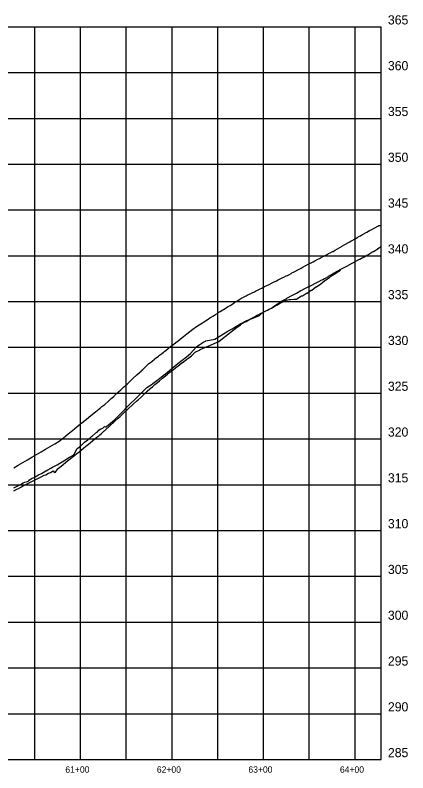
# Model space of a CAD drawing. Extents: x 816928 to 825690, y 436959 to 448212.
# Drawn here: x 818316 to 818745, y 446423 to 447250 of the extents above; entities that cross this region are included whole.
import ezdxf

# ---------------------------------------------------------------- set-up
doc = ezdxf.new("R2010")
doc.units = 0
for name, color, linetype in [('DESIGN - SHEET - Corner Text', 7, 'Continuous'), ('DESIGN - SHEET - Light Grid', 7, 'Continuous'), ('SURVEY - PROFILE - Ground Line with Text', 7, 'Continuous'), ('SURVEY - PROFILE - Utilities - Gas with Text', 7, 'Continuous'), ('SURVEY - PROFILE - Utilities - Water with Text', 7, 'Continuous')]:
    doc.layers.add(name, color=color, linetype=linetype)

msp = doc.modelspace()

# ---------------------------------------------------------------- linework, layer by layer
at = {"layer": 'DESIGN - SHEET - Light Grid'}
for p, q in [((817287.73, 447237.63), (818716.11, 447237.63)), ((817287.73, 447237.63), (818716.11, 447237.63)), ((818337.73, 446437.63), (818337.73, 447237.63)), ((818387.73, 446437.63), (818387.73, 447237.63)), ((818437.73, 446437.63), (818437.73, 447237.63)), ((818487.73, 446437.63), (818487.73, 447237.63)), ((818537.73, 446437.63), (818537.73, 447237.63)), ((818587.73, 446437.63), (818587.73, 447237.63)), ((818637.73, 446437.63), (818637.73, 447237.63)), ((818687.73, 446437.63), (818687.73, 447237.63)), ((818716.11, 446437.63), (818716.11, 447237.63)), ((817287.73, 447187.63), (818716.11, 447187.63)), ((817287.73, 447137.63), (818716.11, 447137.63)), ((817287.73, 447087.63), (818716.11, 447087.63)), ((817287.73, 447037.63), (818716.11, 447037.63)), ((817287.73, 446987.63), (818716.11, 446987.63)), ((817287.73, 446937.63), (818716.11, 446937.63)), ((817287.73, 446887.63), (818716.11, 446887.63)), ((817287.73, 446837.63), (818716.11, 446837.63)), ((817287.73, 446787.63), (818716.11, 446787.63)), ((817287.73, 446737.63), (818716.11, 446737.63)), ((817287.73, 446687.63), (818716.11, 446687.63)), ((817287.73, 446637.63), (818716.11, 446637.63)), ((817287.73, 446587.63), (818716.11, 446587.63)), ((817287.73, 446537.63), (818716.11, 446537.63)), ((817287.73, 446487.63), (818716.11, 446487.63)), ((817287.73, 446437.63), (818716.11, 446437.63)), ((817287.73, 446437.63), (818716.11, 446437.63))]:
    msp.add_line(p, q, dxfattribs=at)
at = {"layer": 'SURVEY - PROFILE - Ground Line with Text'}
msp.add_lwpolyline([(818314.72, 446756.01), (818319.71, 446758.93), (818324.7, 446761.85), (818329.68, 446764.77), (818334.67, 446767.69), (818339.66, 446770.62), (818344.65, 446773.54), (818349.63, 446776.46), (818354.62, 446779.39), (818359.61, 446782.31), (818364.59, 446785.25), (818369.19, 446788.98), (818374.15, 446792.99), (818378.94, 446796.88), (818384.1, 446801.03), (818389.14, 446805.1), (818394.15, 446809.16), (818399.17, 446813.22), (818404.19, 446817.29), (818407.67, 446820.1), (818409.21, 446821.36), (818411.1, 446822.9), (818414.21, 446825.19), (818414.53, 446825.48), (818417.97, 446828.59), (818419, 446829.53), (818419.32, 446829.84), (818421.4, 446831.73), (818423.98, 446834.08), (818424.35, 446834.45), (818424.83, 446834.88), (818428.26, 446838.02), (818428.96, 446838.65), (818429.37, 446839.06), (818431.69, 446841.18), (818433.94, 446843.24), (818434.38, 446843.68), (818435.12, 446844.36), (818438.56, 446847.5), (818438.92, 446847.84), (818439.38, 446848.3), (818441.99, 446850.69), (818443.89, 446852.44), (818444.37, 446852.92), (818445.42, 446853.88), (818448.87, 446857.06), (818449.35, 446857.54), (818452.28, 446860.24), (818453.85, 446861.68), (818454.33, 446862.16), (818455.71, 446863.44), (818458.83, 446866.31), (818459.29, 446866.77), (818462.58, 446869.8), (818464.08, 446871.15), (818466.01, 446872.65), (818468.6, 446874.66), (818469.06, 446875.03), (818469.44, 446875.32), (818472.87, 446877.99), (818473.56, 446878.53), (818474.05, 446878.91), (818476.3, 446880.67), (818478.54, 446882.41), (818479.03, 446882.8), (818479.74, 446883.35), (818483.17, 446886.02), (818483.52, 446886.3), (818484.02, 446886.69), (818486.6, 446888.71), (818488.51, 446890.2), (818489, 446890.59), (818490.03, 446891.39), (818493.52, 446894.11), (818493.99, 446894.48), (818496.89, 446896.75), (818498.53, 446898.03), (818498.97, 446898.38), (818500.33, 446899.44), (818503.96, 446902.28), (818507.19, 446904.81), (818508.59, 446905.9), (818508.94, 446906.19), (818510.62, 446907.5), (818514.3, 446910.31), (818517.48, 446912.32), (818519.24, 446913.42), (818520.92, 446914.48), (818524.44, 446916.69), (818527.1, 446918.37), (818529.12, 446919.64), (818529.77, 446920.05), (818532.44, 446921.73), (818534.07, 446922.76), (818535.11, 446923.41), (818537.78, 446925.09), (818538.44, 446925.51), (818539.04, 446925.88), (818540.45, 446926.75), (818543.12, 446928.41), (818544.04, 446928.99), (818545.79, 446930.08), (818548.46, 446931.75), (818549.04, 446932.12), (818551.13, 446933.42), (818554.02, 446935.25), (818556.46, 446936.79), (818558.58, 446938.12), (818559.13, 446938.47), (818561.8, 446940.13), (818563.99, 446941.49), (818564.47, 446941.73), (818567.14, 446943.08), (818567.91, 446943.47), (818568.82, 446943.92), (818569.81, 446944.41), (818572.48, 446945.73), (818573.85, 446946.41), (818575.15, 446947.05), (818577.82, 446948.38), (818578.86, 446948.91), (818580.48, 446949.71), (818583.15, 446951.04), (818583.86, 446951.4), (818585.82, 446952.38), (818588.85, 446953.9), (818591.16, 446955.05), (818593.83, 446956.39), (818596.5, 446957.73), (818598.78, 446958.87), (818599.28, 446959.12), (818601.84, 446960.38), (818603.81, 446961.35), (818604.51, 446961.69), (818607.17, 446963), (818608.86, 446963.83), (818609.84, 446964.31), (818612.51, 446965.61), (818613.82, 446966.21), (818615.18, 446966.94), (818617.85, 446968.37), (818618.73, 446968.78), (818620.52, 446969.74), (818623.19, 446971.18), (818623.7, 446971.41), (818625.86, 446972.58), (818628.71, 446974.12), (818631.2, 446975.44), (818633.86, 446976.86), (818636.53, 446978.26), (818638.67, 446979.39), (818639.2, 446979.67), (818641.87, 446981.06), (818643.68, 446982.01), (818644.54, 446982.46), (818647.21, 446983.85), (818648.69, 446984.63), (818649.88, 446985.24), (818652.55, 446986.62), (818653.72, 446987.25), (818655.22, 446988.02), (818657.88, 446989.4), (818658.77, 446989.89), (818660.55, 446990.81), (818663.22, 446992.19), (818663.63, 446992.41), (818665.89, 446993.7), (818668.57, 446995.23), (818671.23, 446996.75), (818673.56, 446998.08), (818673.9, 446998.27), (818676.57, 446999.8), (818678.55, 447000.92), (818679.24, 447001.31), (818681.91, 447002.83), (818683.54, 447003.76), (818684.57, 447004.34), (818687.24, 447005.86), (818688.53, 447006.58), (818689.91, 447007.36), (818692.58, 447008.87), (818693.53, 447009.4), (818695.25, 447010.37), (818697.92, 447011.87), (818698.52, 447012.21), (818700.59, 447013.37), (818703.53, 447015.01), (818705.93, 447016.35), (818708.53, 447017.8), (818713.19, 447020.4), (818713.53, 447020.59), (818716.11, 447020.6)], dxfattribs=at)
at = {"layer": 'SURVEY - PROFILE - Utilities - Gas with Text'}
msp.add_lwpolyline([(818315, 446734.29), (818317.06, 446735.25), (818319.99, 446736.9), (818322.04, 446737.84), (818324.99, 446739.51), (818327.02, 446740.45), (818329.67, 446741.04), (818331.31, 446741.8), (818331.99, 446743.05), (818334.98, 446744.74), (818336.97, 446745.66), (818339.97, 446747.36), (818341.95, 446748.28), (818344.97, 446749.98), (818346.93, 446750.9), (818349.96, 446752.61), (818350.23, 446752.76), (818352.21, 446753.84), (818355.22, 446755.54), (818357.23, 446756.63), (818360.21, 446758.32), (818362.24, 446759.42), (818365.2, 446761.09), (818365.75, 446761.47), (818367.81, 446762.59), (818370.72, 446764.58), (818372.89, 446765.76), (818375.68, 446767.67), (818377.96, 446768.89), (818380.65, 446770.72), (818383.73, 446776.86), (818386.41, 446778.79), (818387.8, 446780.01), (818388.39, 446780.54), (818388.39, 446780.54), (818390.4, 446782.35), (818392.26, 446784.02), (818395.64, 446786.58), (818399.69, 446790.25), (818400.55, 446790.8), (818404.42, 446794.31), (818405.9, 446795.12), (818407.67, 446797.04), (818409.29, 446798.23), (818412.01, 446799.22), (818413.99, 446801.08), (818415.73, 446800.58), (818416.23, 446801.08), (818418.25, 446803.12), (818424.93, 446808.5), (818429.35, 446812.93), (818433.75, 446817.35), (818438.15, 446821.77), (818442.54, 446826.18), (818446.93, 446830.59), (818451.31, 446834.98), (818455.68, 446839.37), (818460.04, 446843.76), (818466.05, 446847.51), (818466.62, 446847.95), (818471.28, 446851.57), (818475.92, 446855.17), (818478, 446856.79), (818480.51, 446858.8), (818485.08, 446862.48), (818489.66, 446866.15), (818494.23, 446869.83), (818498.82, 446873.52), (818503.4, 446877.2), (818507.99, 446880.89), (818514.01, 446887.95), (818516.26, 446889.75), (818517.99, 446890.79), (818520.25, 446892.15), (818522.51, 446893.51), (818524.35, 446894.43), (818524.44, 446894.49), (818524.77, 446894.87), (818534.47, 446896.7), (818539.22, 446899.5), (818543.97, 446902.3), (818548.72, 446905.1), (818553.47, 446907.9), (818558.22, 446910.7), (818562.96, 446913.5), (818564.6, 446914.4), (818568, 446916.29), (818569.37, 446916.82), (818574.1, 446918.66), (818578.8, 446920.48), (818583.45, 446922.29), (818587.7, 446926.28), (818592.22, 446928.16), (818593.03, 446928.94), (818597.26, 446930.73), (818600.74, 446933.16), (818602.1, 446933.75), (818602.9, 446934.18), (818604.09, 446934.82), (818607.21, 446936.5), (818610.19, 446938.11), (818611.1, 446938.6), (818615.9, 446939.69), (818617.38, 446939.79), (818617.53, 446939.8), (818620.73, 446940.03), (818622.54, 446940.16), (818623.99, 446940.27), (818624.75, 446940.8), (818626.31, 446941.9), (818629.04, 446943.84), (818630.41, 446943.81), (818634.48, 446946.71), (818635.35, 446946.86), (818639.72, 446950), (818640.38, 446950.2), (818644.94, 446953.48), (818645.46, 446953.68), (818650.14, 446957.05), (818650.16, 446957.06), (818654.87, 446960.46), (818655.29, 446960.81), (818660.09, 446964.27), (818660.97, 446964.84), (818661.32, 446965.13), (818666.56, 446968.51), (818666.82, 446968.72), (818669.94, 446970.73), (818671.91, 446971.77)], dxfattribs=at)
at = {"layer": 'SURVEY - PROFILE - Utilities - Water with Text'}
msp.add_lwpolyline([(818314.92, 446731.06), (818318.22, 446732.88), (818319.23, 446733.29), (818323.19, 446735.47), (818324.29, 446735.92), (818328.15, 446738.03), (818329.37, 446738.52), (818333.12, 446740.56), (818334.44, 446741.09), (818338.08, 446743.06), (818339.52, 446743.62), (818339.79, 446743.64), (818343.15, 446745.45), (818344.61, 446746.12), (818348, 446747.94), (818349.7, 446748.58), (818352.95, 446750.32), (818354.79, 446751), (818357.91, 446752.65), (818359.45, 446750.82), (818360.51, 446751.24), (818362.86, 446754.94), (818363.77, 446755.69), (818366.52, 446757.82), (818368.64, 446759.6), (818371.44, 446761.76), (818373.64, 446763.61), (818376.35, 446765.7), (818378.64, 446767.63), (818381.26, 446769.66), (818383.64, 446771.67), (818386.16, 446773.62), (818388.65, 446775.72), (818391.06, 446777.59), (818393.65, 446779.79), (818395.96, 446781.58), (818398.66, 446783.88), (818400.84, 446785.58), (818403.66, 446787.99), (818405.72, 446789.59), (818407.67, 446791.11), (818408.68, 446792.12), (818410.62, 446793.62), (818413.73, 446796.28), (818413.87, 446796.41), (818415.56, 446798), (818418.76, 446800.92), (818420.58, 446802.63), (818423.77, 446805.55), (818425.59, 446807.26), (818428.78, 446810.18), (818430.61, 446811.89), (818433.8, 446814.81), (818435.62, 446816.52), (818438.81, 446819.44), (818440.64, 446821.16), (818443.83, 446824.07), (818445.66, 446825.79), (818448.84, 446828.7), (818450.67, 446830.42), (818453.85, 446833.33), (818455.69, 446835.06), (818458.87, 446837.96), (818460.7, 446839.69), (818463.43, 446842.22), (818463.87, 446842.57), (818466.29, 446844.53), (818468.87, 446846.88), (818471.82, 446849.24), (818473.88, 446851.09), (818477.31, 446853.8), (818478.89, 446855.2), (818482.75, 446858.22), (818483.9, 446859.23), (818488.15, 446862.54), (818488.91, 446863.2), (818491.68, 446865.34), (818493.43, 446866.65), (818493.92, 446867.06), (818498.53, 446870.52), (818498.93, 446870.86), (818503.61, 446874.36), (818503.95, 446874.64), (818504.48, 446875.01), (818508.98, 446878.38), (818513.56, 446882.64), (818513.81, 446882.87), (818518.35, 446885.01), (818518.52, 446885.12), (818518.66, 446885.18), (818523.47, 446887.43), (818523.97, 446887.65), (818524.01, 446887.66), (818524.35, 446887.93), (818524.44, 446887.97), (818528.89, 446889.77), (818528.92, 446889.79), (818533.8, 446891.9), (818533.87, 446891.95), (818538.71, 446894.05), (818538.82, 446894.12), (818542.75, 446897.19), (818542.89, 446897.28), (818547.67, 446900.99), (818547.84, 446901.1), (818552.58, 446904.79), (818552.79, 446904.92), (818557.49, 446908.57), (818557.74, 446908.73), (818562.41, 446912.35), (818562.69, 446912.53), (818563.74, 446913.11), (818568.49, 446915.77), (818568.68, 446915.86), (818573.51, 446918.57), (818573.62, 446918.63), (818578.54, 446921.39), (818578.56, 446921.4), (818580.03, 446922.22), (818583.44, 446923.95), (818583.72, 446924.09), (818588.3, 446926.41), (818588.73, 446926.62), (818592.85, 446928.71), (818593.82, 446929.2), (818596.42, 446930.51), (818597.76, 446931.42), (818598.71, 446932.07), (818603.06, 446935.02), (818603.42, 446935.26), (818606.41, 446937.29), (818608.18, 446938.31), (818608.23, 446938.33), (818613.01, 446941.07), (818613.18, 446941.15), (818613.77, 446941.48), (818618.6, 446944.12), (818618.71, 446944.19), (818623.6, 446946.87), (818623.66, 446946.9), (818628.6, 446949.61), (818628.6, 446949.61), (818628.92, 446949.79), (818633.46, 446952.14), (818633.58, 446952.22), (818633.61, 446952.2), (818634.97, 446952.88), (818639.68, 446955.21), (818639.83, 446955.28), (818644.54, 446957.62), (818645.05, 446957.98), (818649.77, 446960.35), (818649.99, 446960.46), (818652.57, 446961.76), (818654.43, 446962.84), (818654.7, 446962.62), (818658.58, 446965.1), (818658.8, 446965.21), (818663.68, 446968.35), (818663.71, 446968.37), (818668.03, 446970.67), (818668.11, 446970.72), (818672.93, 446973.29), (818673.07, 446973.36), (818677.83, 446975.9), (818678.03, 446976.01), (818682.72, 446978.51), (818682.99, 446978.65), (818687.62, 446981.12), (818687.95, 446981.3), (818692.51, 446983.73), (818692.91, 446983.94), (818697.4, 446986.34), (818697.87, 446986.58), (818700.73, 446988.11), (818702.33, 446989.1), (818702.81, 446989.39), (818705.93, 446991.33), (818707.39, 446992.21), (818707.74, 446992.42), (818712.49, 446995.32), (818712.7, 446995.45), (818716.11, 446997.53), (818716.11, 446997.53)], dxfattribs=at)

# ---------------------------------------------------------------- texts
at = {"layer": 'DESIGN - SHEET - Corner Text'}
for s, height, p in [('365', 10, (818723.61, 447240.13)), ('360', 10, (818723.61, 447190.13)), ('355', 10, (818723.61, 447140.13)), ('350', 10, (818723.61, 447090.13)), ('345', 10, (818723.61, 447040.13)), ('340', 10, (818723.61, 446990.13)), ('335', 10, (818723.61, 446940.13)), ('330', 10, (818723.61, 446890.13)), ('325', 10, (818723.61, 446840.13)), ('320', 10, (818723.61, 446790.13)), ('315', 10, (818723.61, 446740.13)), ('310', 10, (818723.61, 446690.13)), ('305', 10, (818723.61, 446640.13)), ('300', 10, (818723.61, 446590.13)), ('295', 10, (818723.61, 446540.13)), ('290', 10, (818723.61, 446490.13)), ('285', 10, (818723.61, 446440.13)), ('61+00', 7, (818371.18, 446423.13)), ('62+00', 7, (818471.18, 446423.13)), ('63+00', 7, (818571.18, 446423.13)), ('64+00', 7, (818671.18, 446423.13))]:
    msp.add_text(s, height=height, dxfattribs=at).set_placement(p)

doc.saveas('drawing.dxf')
